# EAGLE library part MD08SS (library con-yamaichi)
YAMAICHI CONNECTOR
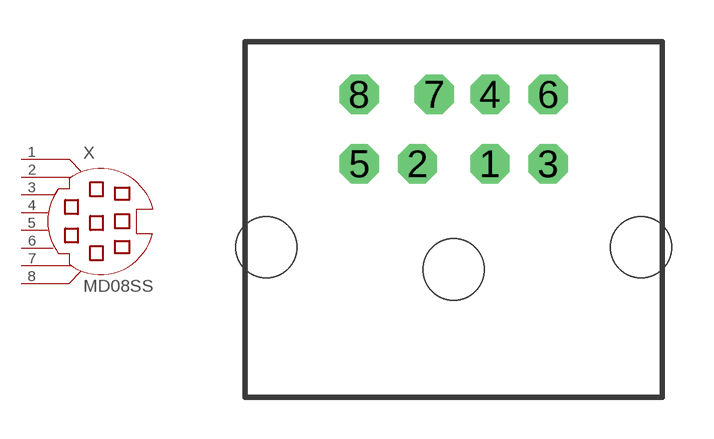
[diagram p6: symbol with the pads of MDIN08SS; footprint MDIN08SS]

Designator prefix X

## MD08SS (OC_FARNELL: unknown; OC_NEWARK: unknown)  [MDIN08SS]
1  1  pas
2  2  pas
3  3  pas
4  4  pas
5  5  pas
6  6  pas
7  7  pas
8  8  pas

## Footprint MDIN08SS (pad centres in mm)
Mini Din YAMAICHI CONNECTOR
drill 0.9 octagon: 1 1.3,8.5; 2 -1.3,8.5; 3 3.4,8.5; 4 1.3,11; 5 -3.4,8.5; 6 3.4,11; 7 -0.7,11; 8 -3.4,11
hole 2.2 at -6.75,5.5
hole 2.2 at 0,4.7
hole 2.2 at 6.75,5.5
